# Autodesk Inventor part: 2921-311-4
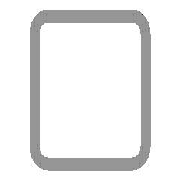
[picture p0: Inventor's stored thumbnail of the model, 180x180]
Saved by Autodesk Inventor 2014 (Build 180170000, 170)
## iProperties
IsCustomPart: 1
Company: NHTSA/VRTC
Created: 2012-02
Part Number: 2921-311-4
Material: Steel, Mild
Description: BENCH FRAME TUBE #4
Document SubType Name: Modeling
Standard: AISC
Designer: Dave Walker
Standards Organization: ANSI
Language: en-US
Size Designation: 1-1/2x1-1/2x1/8 - 6.37
Categories: <MemberInstance><Categories><Category DisplayName="Structural Shapes" InternalName="089c4875-fa83-4c05-b084-43b9cc11f5ed" Mnemonic="GRDR"><CategoryParameter Dis
Stock Number: T.S. 1 1/2 x 1 1/2 x 1/8 x 11.8mm (6.37")
Density: 1 g/cm^3
Project: CHILD SIDE IMPACT SLED
Appearance: Steel
G_L: 6.370 in
Author: Dave Walker
Title: Bench Frame Tube #4
Subject: Child Side Impact Sled
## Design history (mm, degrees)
node "Start plane"
node "End plane"
sketch "Sketch"
  geometry: L1 (-19.05, -12.7)-(-19.05, 12.7); L2 (-12.7, 19.05)-(12.7, 19.05); L3 (19.05, 12.7)-(19.05, -12.7); L4 (12.7, -19.05)-(-12.7, -19.05); L5 (-12.7, 15.875)-(12.7, 15.875); L6 (15.875, 12.7)-(15.875, -12.7); L7 (12.7, -15.875)-(-12.7, -15.875); L8 (-15.875, -12.7)-(-15.875, 12.7); L9 (0, 36.948)-(0, -36.948) reference; L10 (-23.079, 0)-(23.079, 0) reference; A1 r 6.35 centre (-12.7, -12.7) between (-19.05, -12.7) and (-12.7, -19.05); A2 r 6.35 centre (-12.7, 12.7) between (-12.7, 19.05) and (-19.05, 12.7); A3 r 6.35 centre (12.7, 12.7) between (19.05, 12.7) and (12.7, 19.05); A4 r 6.35 centre (12.7, -12.7) between (12.7, -19.05) and (19.05, -12.7); A5 r 3.175 centre (-12.7, 12.7) between (-12.7, 15.875) and (-15.875, 12.7); A6 r 3.175 centre (12.7, 12.7) between (15.875, 12.7) and (12.7, 15.875); A7 r 3.175 centre (12.7, -12.7) between (12.7, -15.875) and (15.875, -12.7); A8 r 3.175 centre (-12.7, -12.7) between (-15.875, -12.7) and (-12.7, -15.875)
  constraints: 16 end point, 16 point on circle, 8 centre point, 8 tangent, 4 parallel, 3 equal radius, 2 perpendicular, 7 other
  dimensions: "d10" = 38.1 distance between parallel lines of L2 L4 (= G_H); "d11" = 38.1 distance between parallel lines of L1 L3 (= G_W); "d12" = 3.175 distance between parallel lines of L3 L6 (= G_T); "d15" = 19.05 distance between parallel lines of L2 L10 (= 0.5 x d10); "d16" = 19.05 distance between parallel lines of L9 L3 (= 0.5 x d11); "d17" = 6.35 radius of A1 (= G_IR)
extrude "Body" new body sketch "Sketch" stored distance "d3" = 161.798 (= G_L); taper "d4" = 0 deg
node "Driven Length"
  sketch "Sketch3"
    geometry: L1 (0, 0)-(10, 0) reference
    constraints: 2 end point, 1 horizontal
  workplane "Work Plane3"
  sketch "Sketch4"
    geometry: L1 (-2, 0)-(12, 0) reference; L2 (-2, 161.798)-(12, 161.798) reference
    dimensions: "d19" = 161.798 distance between parallel lines of L1 L2 (derived)
sketch "Sketch5"
  geometry: L1 (161.798, 31.75)-(0, 31.75) reference; L2 (161.798, -6.35)-(0, -6.35) reference; L3 (0, -6.35)-(6.718, 31.75); L4 (6.718, 31.75)-(0, 31.75); L5 (0, -6.35)-(0, 31.75); 1 further point
  constraints: 6 end point, 1 collinear, 1 perpendicular, 1 point on line
  dimensions: "d20" = 80 deg angle of L2 L3
extrude "Extrusion2" cut sketch "Sketch5" stored distance "d21" = 0; taper "d22" = 0 deg
sketch "Sketch6"
  geometry: L1 (25.4, 0)-(0, 0) reference; 3 further points
  constraints: 1 midpoint, 1 vertical alignment
  dimensions: "d23" = 88.9 distance from line of point (12.7, 88.9) L1
hole "Hole1" sketch "Sketch6" at (12.7, 88.9) diameter "d24" = 4.9784; stored, may be unused: countersink angle "d28" = 82 deg, drill point angle "d30" = 118 deg; dims "d25" = 19.05, "d26" = 9.525, "d27" = 6.35, "d29" = 3.175
body "Solid1"
other parameters: "G_W" = 38.1 [user parameter; used in 1 equation term], "G_H" = 38.1 [user parameter; used in 1 equation term], "G_T" = 3.175 [user parameter; used in 1 equation term], "G_IR" = 6.35 [user parameter; used in 1 equation term], "G_L" = 161.798 (= d19) [user parameter; used in 1 equation term], "G_OFFSET_START" = 0 [user parameter; used in 1 equation term], "G_OFFSET_END" = 0 [user parameter; used in 1 equation term], "d13" = 0 (computed from G_OFFSET_START), "d14" = 161.798 (= G_OFFSET_END + B_L), "B_L" = 161.798 [user parameter; used in 1 equation term], "d18" = 90 deg
